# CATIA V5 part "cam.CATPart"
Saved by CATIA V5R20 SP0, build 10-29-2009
Part number: cam
Bounding box of the stored display mesh (mm): x 0 to 97, y -20 to 20, z -20 to 20
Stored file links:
  C:\Users\bensf\Desktop\bouthaina\cam.CATPart
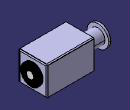
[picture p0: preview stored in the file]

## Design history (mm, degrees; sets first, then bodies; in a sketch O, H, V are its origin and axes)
Sketch1 on yz-plane, origin (0, 0, 0), H (0, 1, 0), V (0, 0, 1)
  circle A1 centre (0, 0) radius 15
  radius A1 = 15
Body1 (main body)
  Pad1: profile Sketch1, direction (1, 0, 0), length 3
  Sketch2 on end face of Pad1, origin (3, 0, 0), H (0, 1, 0), V (0, 0, 1)
    circle A1 centre (0, 0) radius 10
  Pad2: profile Sketch2, direction (1, 0, 0), length 24
  Sketch3 on end face of Pad2, origin (27, 0, 0), H (0, 1, 0), V (0, 0, 1)
    line L1 (20, 20) -> (20, -20)
    line L2 (20, -20) -> (-20, -20)
    line L3 (-20, -20) -> (-20, 20)
    line L4 (-20, 20) -> (20, 20)
    vertical: L1 V, L3 V
    horizontal: L2 H, L4 H
    equidistance: L1 L3 O, L2 L4 O
  Pad3: profile Sketch3, direction (1, 0, 0), length 66
  Chamfer1: length 1, angle 45, on edge [face of Pad3 from Sketch3.L4 | face of Pad3 from Sketch3.L1]; face of Pad3 from Sketch3.L1
  Chamfer2: length 1, second length 1, on face of Pad3 from Sketch3.L4; face of Pad3 from Sketch3.L3; edge [face of Pad3 from Sketch3.L3 | face of Pad3 from Sketch3.L4]
  Chamfer3: length 1, second length 1, on face of Pad3 from Sketch3.L2; end face of Pad3
  Sketch4 on end face of Pad3, origin (93, 0, 0), H (0, 1, 0), V (0, 0, 1)
    circle A1 centre (0, 0) radius 14.1421
  Pad4: profile Sketch4, direction (1, 0, 0), length 3
  Sketch5 on end face of Pad4, origin (96, 0, 0), H (0, 1, 0), V (0, 0, 1)
    circle A1 centre (0, 0) radius 5
    radius A1 = 5
  Pad5: profile Sketch5, direction (1, 0, 0), length 1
